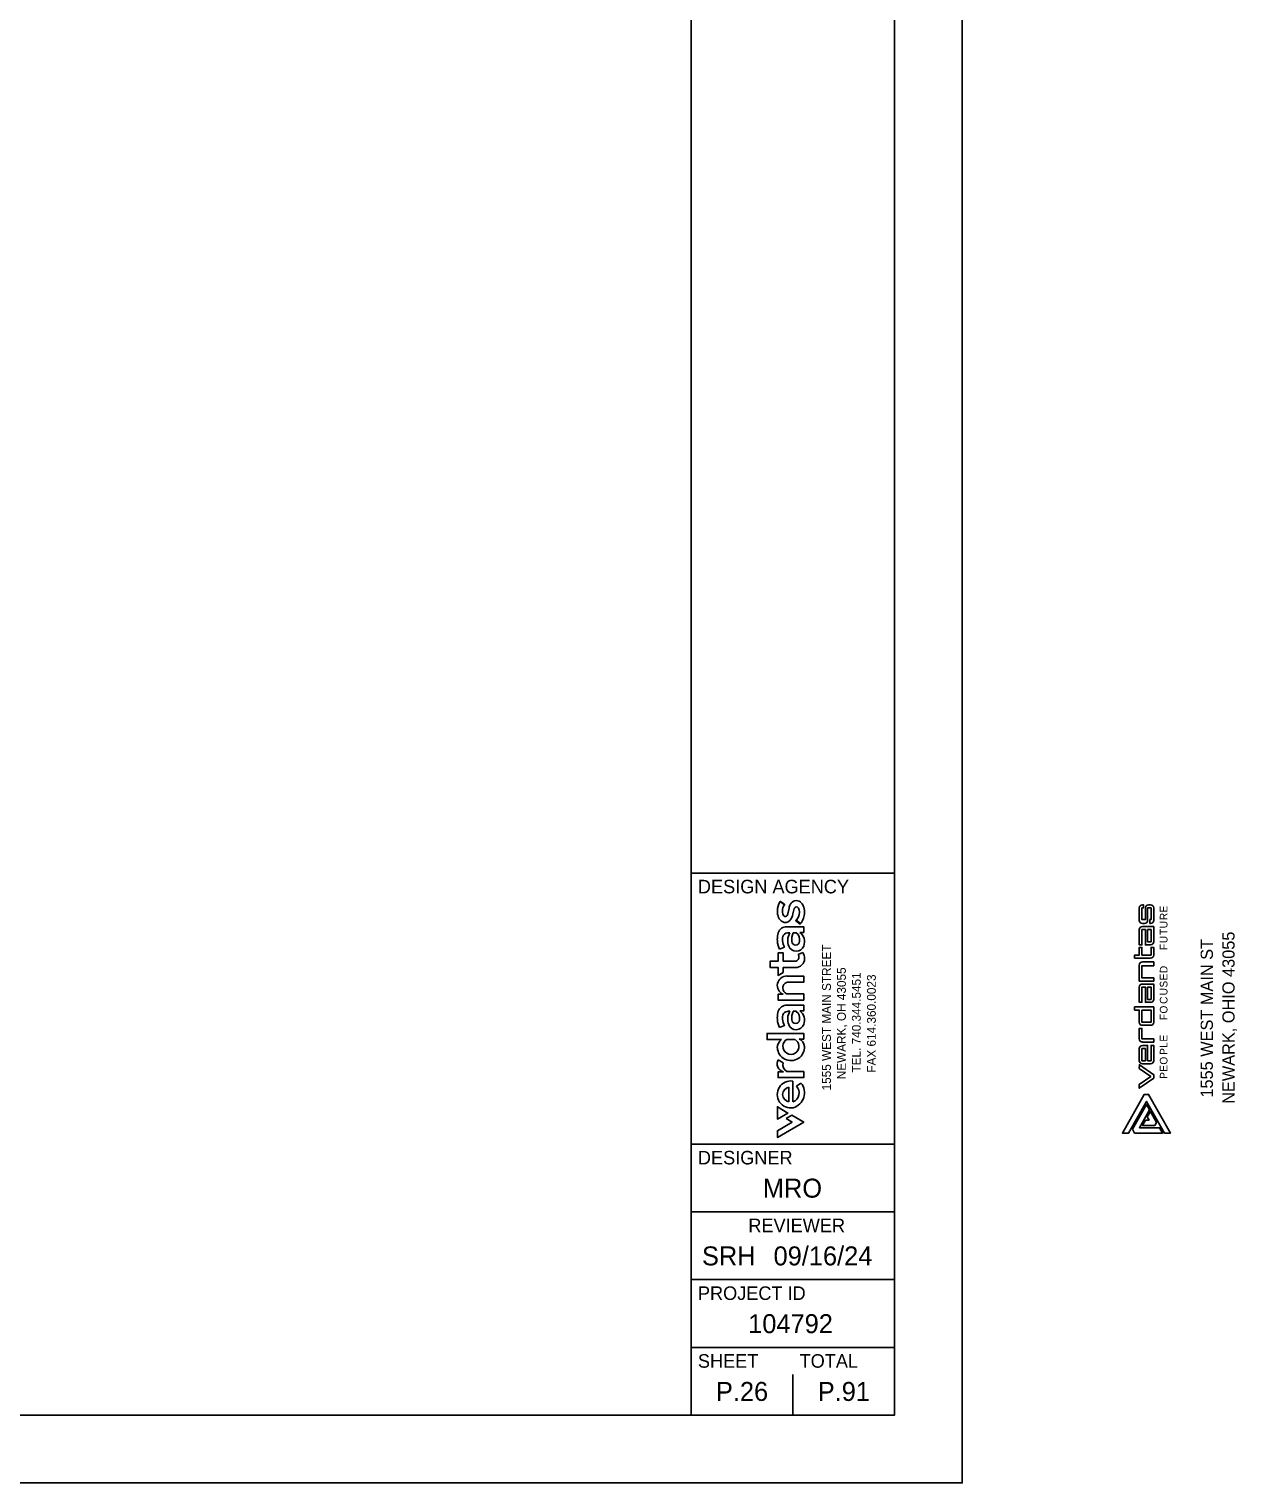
# Model space of a CAD drawing. Extents: x 0 to 36, y 0 to 22.
# Drawn here: x 27.12 to 36.03, y 0 to 10.73 of the extents above; entities that cross this region are included whole.
import ezdxf

# ---------------------------------------------------------------- set-up
doc = ezdxf.new("R2010")
doc.units = 0
for name, color, linetype in [('CS-ANNO-TTLB-LOGO', 7, 'Continuous'), ('Default', 7, 'Continuous'), ('SH_Border', 7, 'Continuous'), ('SH_Cut_Line', 7, 'Continuous'), ('SH_Data', 7, 'Continuous'), ('SH_Text', 7, 'Continuous')]:
    doc.layers.add(name, color=color, linetype=linetype)

msp = doc.modelspace()

# ---------------------------------------------------------------- linework, layer by layer
at = {"layer": 'CS-ANNO-TTLB-LOGO'}
for p, q in [((35.305, 4.243), (35.305, 4.15)), ((35.336, 4.266), (35.328, 4.266)), ((35.389, 4.266), (35.373, 4.266)), ((35.412, 4.15), (35.412, 4.243)), ((35.305, 3.97), (35.305, 4.083)), ((35.328, 4.128), (35.344, 4.128)), ((35.305, 3.546), (35.305, 3.658)), ((35.328, 3.377), (35.389, 3.377)), ((35.412, 3.115), (35.412, 3.228)), ((35.305, 3.205), (35.305, 3.115)), ((35.328, 3.093), (35.389, 3.093))]:
    msp.add_line(p, q, dxfattribs=at)
for points in [[(35.35, 4.243), (35.35, 4.156), (35.325, 4.156), (35.325, 4.243), (35.336, 4.243), (35.336, 4.266)], [(35.367, 4.15), (35.367, 4.243), (35.392, 4.243), (35.392, 4.156), (35.384, 4.156), (35.384, 4.128), (35.389, 4.128)], [(35.389, 3.97), (35.35, 3.97), (35.35, 4.083), (35.325, 4.083), (35.325, 3.97), (35.305, 3.97)], [(35.328, 4.105), (35.412, 4.105), (35.412, 3.993)], [(35.27, 3.894), (35.305, 3.894), (35.305, 3.951), (35.325, 3.951), (35.325, 3.894), (35.392, 3.894), (35.392, 3.951), (35.412, 3.951), (35.412, 3.894)], [(35.389, 3.872), (35.27, 3.872), (35.27, 3.894)], [(35.305, 3.821), (35.305, 3.703), (35.412, 3.703), (35.412, 3.726), (35.325, 3.726), (35.325, 3.816), (35.412, 3.816)], [(35.412, 3.816), (35.412, 3.844), (35.328, 3.844)], [(35.389, 3.546), (35.35, 3.546), (35.35, 3.658), (35.325, 3.658), (35.325, 3.546), (35.305, 3.546)], [(35.328, 3.681), (35.412, 3.681), (35.412, 3.568)], [(35.27, 3.512), (35.27, 3.489), (35.305, 3.489), (35.305, 3.399)], [(35.412, 3.399), (35.412, 3.512), (35.27, 3.512)], [(35.412, 3.276), (35.325, 3.276), (35.325, 3.354), (35.305, 3.354), (35.305, 3.276)], [(35.328, 3.253), (35.412, 3.253), (35.412, 3.276)], [(35.412, 3.228), (35.392, 3.228), (35.392, 3.115), (35.367, 3.115), (35.367, 3.228), (35.328, 3.228)]]:
    msp.add_lwpolyline(points, dxfattribs=at)
for points in [[(35.367, 4.083), (35.392, 4.083), (35.392, 3.993), (35.367, 3.993)], [(35.367, 3.658), (35.392, 3.658), (35.392, 3.568), (35.367, 3.568)], [(35.325, 3.489), (35.325, 3.399), (35.392, 3.399), (35.392, 3.489)], [(35.35, 3.205), (35.325, 3.205), (35.325, 3.115), (35.35, 3.115)], [(35.39, 2.999), (35.305, 2.94), (35.305, 2.912), (35.412, 2.987), (35.412, 3.011), (35.306, 3.085), (35.305, 3.058)]]:
    msp.add_lwpolyline(points, close=True, dxfattribs=at)
for centre, start, end in [((35.328, 4.243), 90, 180), ((35.373, 4.243), 90, 180), ((35.389, 4.243), 360, 90), ((35.328, 4.15), 180, 270), ((35.328, 4.083), 90, 180), ((35.344, 4.15), 270, 0), ((35.389, 4.15), 270, 0), ((35.389, 3.993), 270, 360), ((35.389, 3.894), 270, 360), ((35.328, 3.821), 90, 180), ((35.328, 3.658), 90, 180), ((35.389, 3.568), 270, 360), ((35.328, 3.399), 180, 270), ((35.389, 3.399), 270, 0), ((35.328, 3.276), 180, 270), ((35.328, 3.205), 90, 180), ((35.328, 3.115), 180, 270), ((35.389, 3.115), 270, 0)]:
    msp.add_arc(centre, 0.0225, start, end, dxfattribs=at)
at = {"layer": 'Default'}
for p, q in [((35.305, 4.243), (35.305, 4.15)), ((35.389, 4.266), (35.373, 4.266)), ((35.412, 4.15), (35.412, 4.243)), ((35.328, 4.128), (35.344, 4.128)), ((35.328, 3.377), (35.389, 3.377)), ((35.305, 3.205), (35.305, 3.115)), ((35.328, 3.093), (35.389, 3.093)), ((35.255, 2.609), (35.358, 2.792)), ((35.358, 2.792), (35.381, 2.752)), ((35.381, 2.752), (35.306, 2.621)), ((35.27, 2.581), (35.255, 2.609)), ((35.477, 2.581), (35.27, 2.581)), ((35.306, 2.621), (35.455, 2.621)), ((35.455, 2.621), (35.477, 2.581))]:
    msp.add_line(p, q, dxfattribs=at)
for points in [[(35.35, 4.243), (35.35, 4.156), (35.325, 4.156), (35.325, 4.243), (35.336, 4.243), (35.336, 4.266), (35.328, 4.266)], [(35.367, 4.15), (35.367, 4.243), (35.392, 4.243), (35.392, 4.156), (35.384, 4.156), (35.384, 4.128), (35.389, 4.128)], [(35.305, 4.083), (35.305, 3.97), (35.325, 3.97), (35.325, 4.083), (35.35, 4.083), (35.35, 3.97), (35.389, 3.97)], [(35.412, 3.993), (35.412, 4.105), (35.328, 4.105)], [(35.412, 3.894), (35.412, 3.951), (35.392, 3.951), (35.392, 3.894), (35.325, 3.894), (35.325, 3.951), (35.305, 3.951), (35.305, 3.894), (35.27, 3.894), (35.27, 3.872), (35.389, 3.872)], [(35.305, 3.821), (35.305, 3.703), (35.412, 3.703), (35.412, 3.726), (35.325, 3.726), (35.325, 3.816), (35.412, 3.816), (35.412, 3.844), (35.328, 3.844)], [(35.305, 3.658), (35.305, 3.546), (35.325, 3.546), (35.325, 3.658), (35.35, 3.658), (35.35, 3.546), (35.389, 3.546)], [(35.412, 3.568), (35.412, 3.681), (35.328, 3.681)], [(35.412, 3.399), (35.412, 3.512), (35.27, 3.512), (35.27, 3.489), (35.305, 3.489), (35.305, 3.399)], [(35.328, 3.253), (35.412, 3.253), (35.412, 3.276), (35.325, 3.276), (35.325, 3.354), (35.305, 3.354), (35.305, 3.276)], [(35.412, 3.115), (35.412, 3.228), (35.392, 3.228), (35.392, 3.115), (35.367, 3.115), (35.367, 3.228), (35.328, 3.228)]]:
    msp.add_lwpolyline(points, dxfattribs=at)
for points in [[(35.392, 4.083), (35.392, 3.993), (35.367, 3.993), (35.367, 4.083)], [(35.392, 3.658), (35.392, 3.568), (35.367, 3.568), (35.367, 3.658)], [(35.325, 3.489), (35.392, 3.489), (35.392, 3.399), (35.325, 3.399)], [(35.35, 3.205), (35.35, 3.115), (35.325, 3.115), (35.325, 3.205)], [(35.305, 2.94), (35.305, 2.912), (35.412, 2.987), (35.412, 3.011), (35.306, 3.085), (35.305, 3.058), (35.39, 2.999)], [(35.358, 2.815), (35.49, 2.581), (35.535, 2.581), (35.374, 2.867), (35.342, 2.867), (35.181, 2.581), (35.226, 2.581)], [(35.226, 2.581), (35.358, 2.815), (35.49, 2.581), (35.535, 2.581), (35.374, 2.867), (35.342, 2.867), (35.181, 2.581)], [(35.255, 2.609), (35.27, 2.581), (35.477, 2.581), (35.455, 2.621), (35.306, 2.621), (35.381, 2.752), (35.358, 2.792)], [(35.351, 2.677), (35.329, 2.637), (35.419, 2.637), (35.432, 2.66), (35.387, 2.741), (35.364, 2.701), (35.378, 2.677)], [(35.351, 2.677), (35.378, 2.677), (35.364, 2.701), (35.387, 2.741), (35.432, 2.66), (35.419, 2.637), (35.329, 2.637)]]:
    msp.add_lwpolyline(points, close=True, dxfattribs=at)
for centre, start, end in [((35.328, 4.243), 90, 180), ((35.373, 4.243), 90, 180), ((35.389, 4.243), 360, 90), ((35.328, 4.15), 180, 270), ((35.328, 4.083), 90, 180), ((35.344, 4.15), 270, 0), ((35.389, 4.15), 270, 0), ((35.389, 3.993), 270, 0), ((35.389, 3.894), 270, 0), ((35.328, 3.821), 90, 180), ((35.328, 3.658), 90, 180), ((35.389, 3.568), 270, 0), ((35.328, 3.399), 180, 270), ((35.389, 3.399), 270, 0), ((35.328, 3.276), 180, 270), ((35.328, 3.205), 90, 180), ((35.328, 3.115), 180, 270), ((35.389, 3.115), 270, 0)]:
    msp.add_arc(centre, 0.0225, start, end, dxfattribs=at)
at = {"layer": 'SH_Border'}
for p, q in [((32, 0.5), (32, 21.5)), ((32, 4.5), (33.5, 4.5)), ((32, 2.5), (33.5, 2.5)), ((32, 2), (33.5, 2)), ((32, 1.5), (33.5, 1.5)), ((32, 1), (33.5, 1))]:
    msp.add_line(p, q, dxfattribs=at)
msp.add_lwpolyline([(1.5, 21.5), (33.5, 21.5), (33.5, 0.5), (1.5, 0.5)], close=True, dxfattribs=at)
at = {"layer": 'SH_Cut_Line'}
msp.add_lwpolyline([(0, 0), (34, 0), (34, 22), (0, 22)], close=True, dxfattribs=at)
at = {"layer": 'SH_Data'}
for p, q in [((32.75, 3.5), (32.75, 3.5)), ((32.75, 0.5), (32.75, 0.8)), ((32.375, 0.675), (32.375, 0.675))]:
    msp.add_line(p, q, dxfattribs=at)
at = {"layer": 'SH_Text'}
for p, q in [((32.688, 4.266), (32.657, 4.29)), ((32.722, 4.24), (32.715, 4.209)), ((32.751, 4.199), (32.756, 4.219)), ((32.774, 4.151), (32.807, 4.127)), ((32.711, 4.058), (32.727, 4.058)), ((32.753, 4.058), (32.776, 4.058)), ((32.648, 3.95), (32.652, 3.938)), ((32.825, 3.914), (32.79, 3.898)), ((32.711, 3.48), (32.727, 3.48)), ((32.753, 3.48), (32.776, 3.48)), ((32.648, 3.372), (32.652, 3.36)), ((32.706, 3.271), (32.766, 3.271)), ((32.679, 3.1), (32.642, 3.122)), ((32.721, 2.92), (32.721, 2.812)), ((32.751, 2.811), (32.751, 2.964)), ((32.81, 2.95), (32.778, 2.928))]:
    msp.add_line(p, q, dxfattribs=at)
for points in [[(32.689, 4.269), (32.658, 4.291), (32.657, 4.29)], [(32.688, 4.266), (32.689, 4.269)], [(32.722, 4.24), (32.715, 4.209)], [(32.751, 4.199), (32.756, 4.219)], [(32.801, 4.062), (32.831, 4.062), (32.831, 4.104), (32.706, 4.104)], [(32.801, 4.062), (32.831, 4.062), (32.831, 4.104), (32.706, 4.104)], [(32.774, 4.151), (32.772, 4.148), (32.803, 4.123), (32.807, 4.127)], [(32.711, 4.058), (32.727, 4.058)], [(32.776, 4.058), (32.753, 4.058)], [(32.762, 3.849), (32.68, 3.849), (32.68, 3.91), (32.641, 3.91), (32.641, 3.849), (32.582, 3.849), (32.582, 3.803), (32.641, 3.803), (32.641, 3.744), (32.68, 3.767), (32.68, 3.803), (32.77, 3.803)], [(32.762, 3.849), (32.68, 3.849), (32.68, 3.91), (32.641, 3.91), (32.641, 3.849), (32.582, 3.849), (32.582, 3.803), (32.641, 3.803), (32.641, 3.744), (32.68, 3.767), (32.68, 3.803), (32.77, 3.803)], [(32.648, 3.95), (32.652, 3.938)], [(32.652, 3.938), (32.688, 3.953), (32.684, 3.962)], [(32.652, 3.938), (32.688, 3.953), (32.684, 3.962)], [(32.825, 3.914), (32.79, 3.898)], [(32.72, 3.694), (32.831, 3.694), (32.831, 3.74), (32.707, 3.74)], [(32.72, 3.694), (32.831, 3.694), (32.831, 3.74), (32.707, 3.74)], [(32.678, 3.605), (32.641, 3.605), (32.641, 3.563), (32.831, 3.563), (32.831, 3.608), (32.704, 3.608)], [(32.678, 3.605), (32.641, 3.605), (32.641, 3.563), (32.831, 3.563), (32.831, 3.608), (32.704, 3.608)], [(32.801, 3.483), (32.831, 3.483), (32.831, 3.525), (32.706, 3.525)], [(32.801, 3.483), (32.831, 3.483), (32.831, 3.525), (32.706, 3.525)], [(32.711, 3.48), (32.727, 3.48)], [(32.776, 3.48), (32.753, 3.48)], [(32.648, 3.372), (32.652, 3.36)], [(32.652, 3.36), (32.688, 3.374), (32.684, 3.384)], [(32.652, 3.36), (32.688, 3.374), (32.684, 3.384)], [(32.667, 3.271), (32.56, 3.271), (32.56, 3.317), (32.831, 3.317), (32.831, 3.275), (32.798, 3.275)], [(32.798, 3.275), (32.831, 3.275), (32.831, 3.317), (32.56, 3.317), (32.56, 3.271), (32.667, 3.271)], [(32.706, 3.271), (32.766, 3.271)], [(32.679, 3.1), (32.642, 3.122)], [(32.682, 3.033), (32.641, 3.033), (32.641, 2.991), (32.831, 2.991), (32.831, 3.035), (32.705, 3.035)], [(32.682, 3.033), (32.641, 3.033), (32.641, 2.991), (32.831, 2.991), (32.831, 3.035), (32.705, 3.035)], [(32.721, 2.812), (32.721, 2.92)], [(32.751, 2.811), (32.751, 2.964)], [(32.81, 2.95), (32.778, 2.928)], [(32.636, 2.775), (32.636, 2.684), (32.714, 2.729), (32.636, 2.775)], [(32.7, 2.688), (32.744, 2.662), (32.636, 2.599), (32.636, 2.549), (32.831, 2.662), (32.743, 2.713), (32.7, 2.688)]]:
    msp.add_lwpolyline(points, dxfattribs=at)
for points in [[(32.714, 2.729), (32.636, 2.684), (32.636, 2.775)], [(32.7, 2.688), (32.744, 2.662), (32.636, 2.599), (32.636, 2.549), (32.831, 2.662), (32.743, 2.713)]]:
    msp.add_lwpolyline(points, close=True, dxfattribs=at)
for centre, radius, start, end in [((32.776, 4.247), 0.0493, 52.7092, 154.2166), ((32.776, 4.247), 0.0493, 52.7092, 154.2166), ((32.767, 4.219), 0.131, 147.2233, 179.842), ((32.767, 4.219), 0.131, 147.2233, 179.842), ((32.75, 4.217), 0.114, 179.0109, 203.56), ((32.75, 4.217), 0.114, 179.0109, 203.56), ((32.768, 4.216), 0.0948, 148.1233, 178.1135), ((32.768, 4.216), 0.0948, 148.1233, 178.1135), ((32.744, 4.218), 0.0702, 179.0539, 195.6921), ((32.744, 4.218), 0.0702, 179.0539, 195.6921), ((32.709, 4.207), 0.0335, 193.8561, 223.7191), ((32.709, 4.207), 0.0335, 193.8561, 223.7191), ((32.695, 4.194), 0.0148, 224.7822, 330.4366), ((32.695, 4.194), 0.0148, 224.7822, 330.4366), ((32.635, 4.224), 0.0819, 332.9002, 349.3831), ((32.635, 4.224), 0.0819, 332.9002, 349.3831), ((32.849, 4.212), 0.13, 154.0447, 167.2149), ((32.849, 4.212), 0.13, 154.0447, 167.2149), ((32.648, 4.217), 0.105, 320.1259, 349.7023), ((32.648, 4.217), 0.105, 320.1259, 349.7023), ((32.849, 4.203), 0.0949, 158.1863, 170.6328), ((32.849, 4.203), 0.0949, 158.1863, 170.6328), ((32.777, 4.234), 0.0165, 26.9165, 163.602), ((32.777, 4.234), 0.0165, 26.9165, 163.602), ((32.705, 4.214), 0.0932, 317.363, 356.9244), ((32.705, 4.214), 0.0932, 317.363, 356.9244), ((32.733, 4.212), 0.0655, 357.0077, 26.3112), ((32.733, 4.212), 0.0655, 357.0077, 26.3112), ((32.761, 4.231), 0.0711, 22.8278, 50.7157), ((32.761, 4.231), 0.0711, 22.8278, 50.7157), ((32.707, 4.209), 0.129, 320.5166, 0.4341), ((32.707, 4.209), 0.129, 320.5166, 0.4341), ((32.717, 4.212), 0.12, 359.0192, 22.9257), ((32.717, 4.212), 0.12, 359.0192, 22.9257), ((32.704, 4.04), 0.0639, 88.076, 162.8642), ((32.704, 4.04), 0.0639, 88.076, 162.8642), ((32.707, 4.198), 0.067, 203.3692, 237.807), ((32.707, 4.198), 0.067, 203.3692, 237.807), ((32.695, 4.181), 0.0458, 238.9453, 317.6829), ((32.695, 4.181), 0.0458, 238.9453, 317.6829), ((32.764, 4.016), 0.128, 160.8128, 180.9317), ((32.764, 4.016), 0.128, 160.8128, 180.9317), ((32.834, 4.018), 0.199, 180.9467, 199.8354), ((32.834, 4.018), 0.199, 180.9467, 199.8354), ((32.739, 4.012), 0.0647, 163.2522, 179.9971), ((32.739, 4.012), 0.0647, 163.2522, 179.9971), ((32.826, 4.016), 0.152, 181.6616, 200.8714), ((32.826, 4.016), 0.152, 181.6616, 200.8714), ((32.713, 4.021), 0.0374, 92.9671, 165.223), ((32.713, 4.021), 0.0374, 92.9671, 165.223), ((32.82, 4.001), 0.108, 148.3497, 202.4708), ((32.82, 4.001), 0.108, 148.3497, 202.4708), ((32.847, 4.012), 0.105, 153.8372, 188.8746), ((32.847, 4.012), 0.105, 153.8372, 188.8746), ((32.771, 3.997), 0.0281, 182.327, 355.3778), ((32.771, 3.997), 0.0281, 182.327, 355.3778), ((32.737, 4.008), 0.0637, 348.1247, 52.3678), ((32.737, 4.008), 0.0637, 348.1247, 52.3678), ((32.751, 3.993), 0.0857, 338.2774, 53.7949), ((32.751, 3.993), 0.0857, 338.2774, 53.7949), ((32.775, 3.982), 0.0592, 201.6764, 339.7268), ((32.775, 3.982), 0.0592, 201.6764, 339.7268), ((32.764, 3.88), 0.0314, 265.0692, 356.3548), ((32.764, 3.88), 0.0314, 265.0692, 356.3548), ((32.772, 3.867), 0.0642, 267.8641, 1.6213), ((32.772, 3.867), 0.0642, 267.8641, 1.6213), ((32.752, 3.877), 0.0432, 1.8638, 29.9651), ((32.752, 3.877), 0.0432, 1.8638, 29.9651), ((32.742, 3.87), 0.0939, 359.5424, 28.2495), ((32.742, 3.87), 0.0939, 359.5424, 28.2495), ((32.706, 3.67), 0.0703, 88.9896, 246.9111), ((32.706, 3.67), 0.0703, 88.9896, 246.9111), ((32.72, 3.654), 0.0434, 137.3049, 182.9688), ((32.72, 3.654), 0.0434, 137.3049, 182.9688), ((32.724, 3.652), 0.0477, 180.3466, 244.9113), ((32.724, 3.652), 0.0477, 180.3466, 244.9113), ((32.717, 3.651), 0.0433, 86.9739, 132.7421), ((32.717, 3.651), 0.0433, 86.9739, 132.7421), ((32.764, 3.438), 0.128, 160.8128, 180.9317), ((32.764, 3.438), 0.128, 160.8128, 180.9317), ((32.834, 3.439), 0.199, 180.9467, 199.8354), ((32.834, 3.439), 0.199, 180.9467, 199.8354), ((32.704, 3.461), 0.0639, 88.076, 162.8642), ((32.704, 3.461), 0.0639, 88.076, 162.8642), ((32.739, 3.433), 0.0647, 163.2522, 179.9971), ((32.739, 3.433), 0.0647, 163.2522, 179.9971), ((32.826, 3.438), 0.152, 181.6616, 200.8714), ((32.826, 3.438), 0.152, 181.6616, 200.8714), ((32.713, 3.442), 0.0374, 92.9671, 165.223), ((32.713, 3.442), 0.0374, 92.9671, 165.223), ((32.82, 3.423), 0.108, 148.3497, 202.4708), ((32.82, 3.423), 0.108, 148.3497, 202.4708), ((32.847, 3.433), 0.105, 153.8372, 188.8746), ((32.847, 3.433), 0.105, 153.8372, 188.8746), ((32.737, 3.429), 0.0637, 348.1247, 52.3678), ((32.737, 3.429), 0.0637, 348.1247, 52.3678), ((32.751, 3.414), 0.0857, 338.2774, 53.7949), ((32.751, 3.414), 0.0857, 338.2774, 53.7949), ((32.775, 3.403), 0.0592, 201.6764, 339.7268), ((32.775, 3.403), 0.0592, 201.6764, 339.7268), ((32.771, 3.418), 0.0281, 182.327, 355.3778), ((32.771, 3.418), 0.0281, 182.327, 355.3778), ((32.707, 3.212), 0.0714, 124.2843, 181.2723), ((32.707, 3.212), 0.0714, 124.2843, 181.2723), ((32.736, 3.216), 0.1, 182.7719, 2.9779), ((32.736, 3.216), 0.1, 182.7719, 2.9779), ((32.736, 3.221), 0.0595, 176.4529, 5.055), ((32.736, 3.221), 0.0595, 176.4529, 5.055), ((32.735, 3.221), 0.0586, 119.9007, 175.5797), ((32.735, 3.221), 0.0586, 119.9007, 175.5797), ((32.737, 3.22), 0.0588, 6.0666, 60.041), ((32.737, 3.22), 0.0588, 6.0666, 60.041), ((32.769, 3.215), 0.0671, 5.3084, 64.5252), ((32.769, 3.215), 0.0671, 5.3084, 64.5252), ((32.697, 3.094), 0.0628, 152.6524, 255.2929), ((32.697, 3.094), 0.0628, 152.6524, 255.2929), ((32.731, 3.083), 0.0545, 162.1384, 242.0408), ((32.731, 3.083), 0.0545, 162.1384, 242.0408), ((32.735, 2.866), 0.0996, 81.0446, 280.2577), ((32.735, 2.866), 0.0996, 81.0446, 280.2577), ((32.729, 2.866), 0.0543, 98.8378, 261.1622), ((32.729, 2.866), 0.0543, 98.8378, 261.1622), ((32.725, 2.879), 0.072, 290.9232, 42.7391), ((32.725, 2.879), 0.072, 290.9232, 42.7391), ((32.722, 2.878), 0.114, 285.6668, 39.3699), ((32.722, 2.878), 0.114, 285.6668, 39.3699)]:
    msp.add_arc(centre, radius, start, end, dxfattribs=at)

# ---------------------------------------------------------------- texts
at = {"layer": 'Default'}
for s, p in [('E', (35.513, 4.208)), ('R', (35.513, 4.152)), ('U', (35.513, 4.092)), ('T', (35.513, 4.043)), ('U', (35.513, 3.982)), ('F', (35.513, 3.931)), ('D', (35.513, 3.761)), ('E', (35.513, 3.708)), ('S', (35.513, 3.655)), ('U', (35.513, 3.597)), ('C', (35.513, 3.534)), ('O', (35.513, 3.463)), ('F', (35.513, 3.414)), ('E', (35.513, 3.256)), ('L', (35.513, 3.21)), ('P', (35.513, 3.158)), ('O', (35.513, 3.086)), ('E', (35.513, 3.033)), ('P', (35.513, 2.981))]:
    msp.add_text(s, height=0.0563, rotation=90, dxfattribs=at).set_placement(p)
at = {"layer": 'SH_Data'}
for s, height, p in [('DESIGN AGENCY', 0.1, (32.05, 4.35)), ('DESIGNER', 0.1, (32.05, 2.35)), ('MRO', 0.14, (32.529, 2.105)), ('REVIEWER', 0.1, (32.422, 1.85)), ('SRH', 0.14, (32.08, 1.605)), ('09/16/24', 0.14, (32.608, 1.605)), ('PROJECT ID', 0.1, (32.05, 1.35)), ('104792', 0.14, (32.421, 1.105)), ('SHEET', 0.1, (32.05, 0.85)), ('TOTAL', 0.1, (32.8, 0.85)), ('P.26', 0.14, (32.183, 0.605)), ('P.91', 0.14, (32.934, 0.605))]:
    msp.add_text(s, height=height, dxfattribs=at).set_placement(p)
at = {"layer": 'SH_Text'}
for s, height, p in [('1555 WEST MAIN STREET', 0.06497, (33.031, 2.896)), ('1555 WEST MAIN ST', 0.09, (35.848, 2.843)), ('NEWARK, OHIO 43055', 0.09, (36.008, 2.797)), ('NEWARK, OH 43055', 0.06497, (33.141, 2.978)), ('TEL. 740.344.5451', 0.06497, (33.251, 3.028)), ('FAX 614.360.0023', 0.06497, (33.362, 3.027))]:
    msp.add_text(s, height=height, rotation=90, dxfattribs=at).set_placement(p)

doc.saveas('drawing.dxf')
